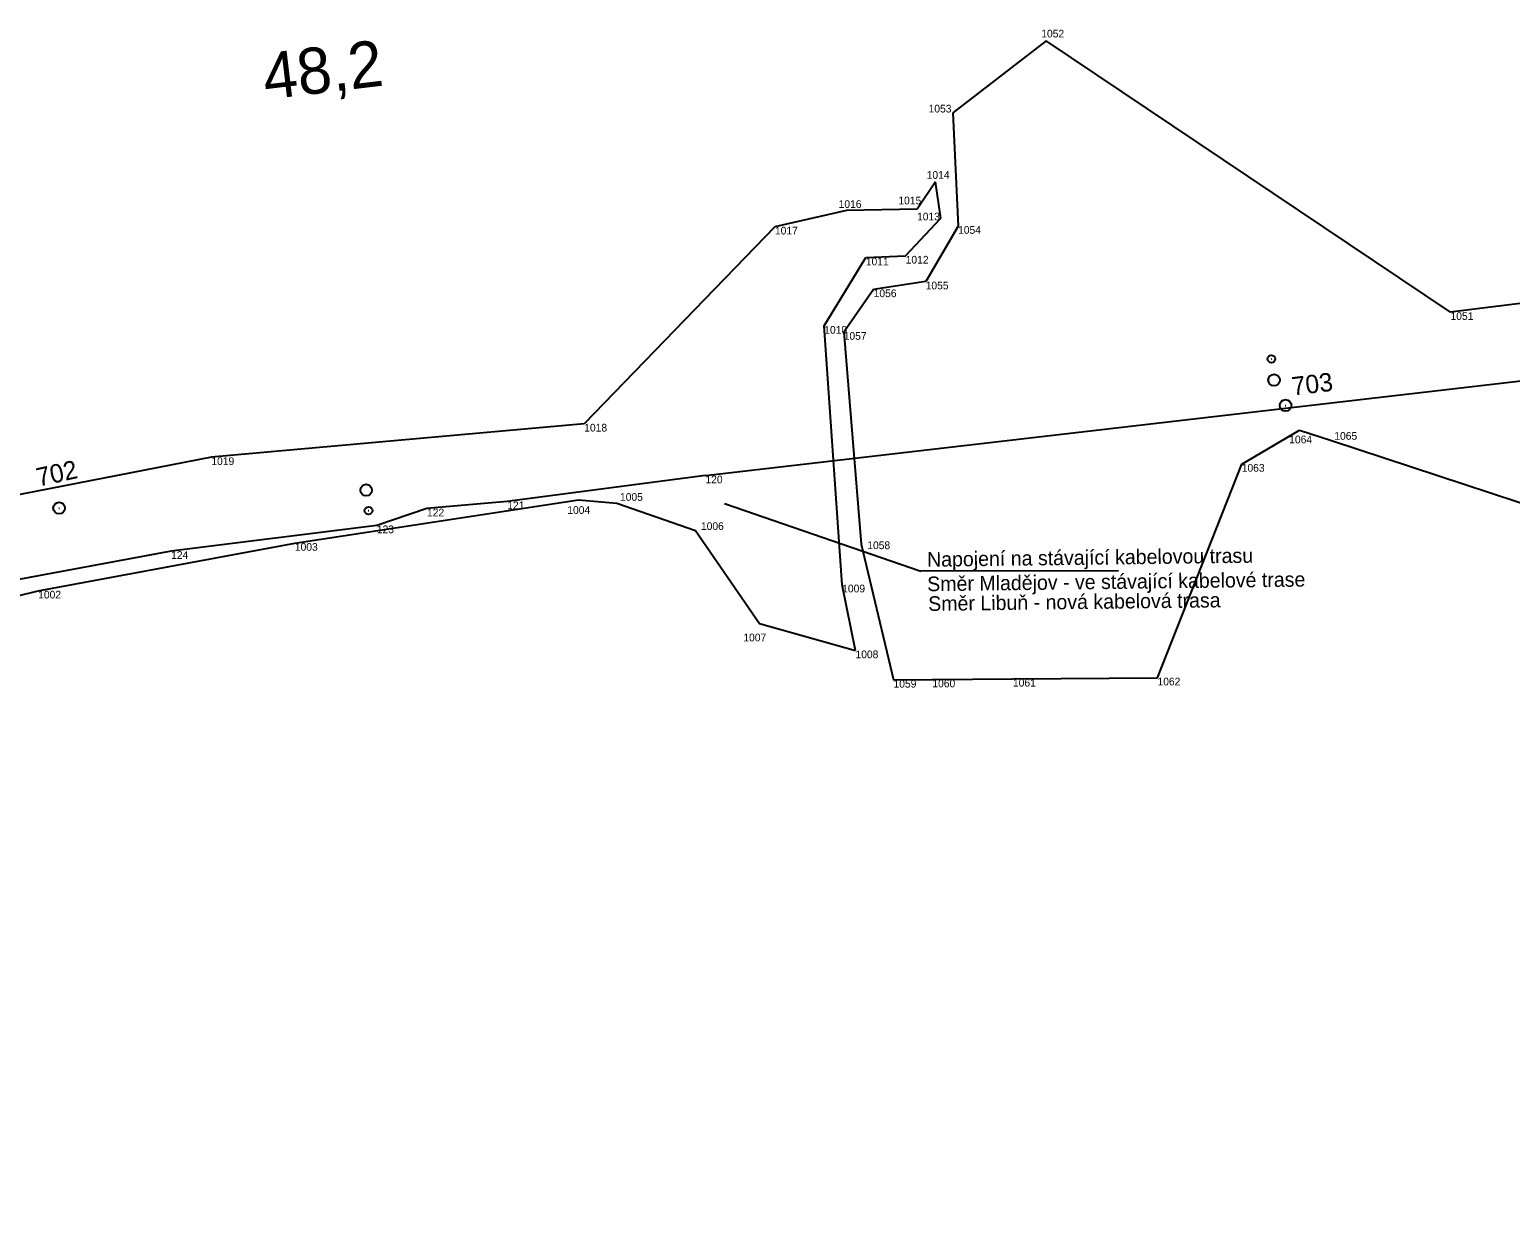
# Model space of a CAD drawing. Extents: x -679938 to -678300, y -1007495 to -1006487.
# Drawn here: x -679308.8 to -679116.3, y -1007081 to -1006925.4 of the extents above; entities that cross this region are included whole.
import ezdxf

# ---------------------------------------------------------------- set-up
doc = ezdxf.new("R2010")
doc.units = 0
for name, color, linetype in [('SSZT nové - lomové body', 7, 'Continuous'), ('SSZT_nové', 7, 'Continuous'), ('Stávající ŽBP', 7, 'Continuous'), ('SŽDC', 7, 'Continuous'), ('SŽDC - body', 7, 'Continuous'), ('Vrstva 7', 7, 'Continuous')]:
    doc.layers.add(name, color=color, linetype=linetype)

msp = doc.modelspace()

# ---------------------------------------------------------------- linework, layer by layer
at = {"layer": 'SSZT nové - lomové body'}
for p, q in [((-679220.94, -1006983.3), (-679220.94, -1006983.3)), ((-679220.94, -1006983.3), (-679220.94, -1006983.3)), ((-679246.69, -1006986.66), (-679246.69, -1006986.66)), ((-679257.12, -1006987.59), (-679257.12, -1006987.59)), ((-679263.64, -1006989.78), (-679263.64, -1006989.78)), ((-679290.37, -1006993.12), (-679290.37, -1006993.12))]:
    msp.add_line(p, q, dxfattribs=at)
at = {"layer": 'SSZT_nové'}
for p in [(-679218.45, -1006986.93), (-679167.27, -1006995.67)]:
    msp.add_line(p, (-679192.94, -1006995.71), dxfattribs=at)
for points in [[(-679220.94, -1006983.3), (-679079.13, -1006966.84), (-679050.01, -1006961.07), (-679026.5, -1006953.22), (-679002.7, -1006941.83), (-678982.82, -1006929.34)], [(-679220.94, -1006983.3), (-679246.69, -1006986.66), (-679257.12, -1006987.59), (-679263.64, -1006989.78), (-679290.37, -1006993.12), (-679314.41, -1006997.58), (-679339.65, -1007005.39), (-679347.7, -1007008.02), (-679359.02, -1007014.04), (-679374.65, -1007024.99), (-679381.38, -1007029.97), (-679393.78, -1007041.11), (-679406.46, -1007055.73), (-679421.12, -1007075.95), (-679445.24, -1007119.78), (-679458.14, -1007141.2), (-679468.52, -1007158.46), (-679472.05, -1007161.83), (-679488.31, -1007180.65), (-679506.94, -1007197.49), (-679535.13, -1007216.77)]]:
    msp.add_lwpolyline(points, dxfattribs=at)
at = {"layer": 'Stávající ŽBP'}
for p, q in [((-679145.61, -1006974.18), (-679145.51, -1006974.17)), ((-679304.97, -1006987.53), (-679304.87, -1006987.51))]:
    msp.add_line(p, q, dxfattribs=at)
for centre in [(-679145.56, -1006974.18), (-679304.92, -1006987.52)]:
    msp.add_circle(centre, 0.756, dxfattribs=at)
at = {"layer": 'SŽDC'}
for p, q in [((-679176.67, -1006926.8), (-679188.77, -1006936.15)), ((-679124.12, -1006962.07), (-679176.67, -1006926.8)), ((-679188.77, -1006936.15), (-679188.11, -1006950.88)), ((-679191.04, -1006945.11), (-679193.44, -1006948.7)), ((-679190.34, -1006949.86), (-679191.04, -1006945.11)), ((-679202.6, -1006948.84), (-679211.91, -1006950.97)), ((-679193.44, -1006948.7), (-679202.6, -1006948.84)), ((-679194.92, -1006954.75), (-679190.34, -1006949.86)), ((-679188.11, -1006950.88), (-679192.32, -1006958.1)), ((-679211.91, -1006950.97), (-679236.69, -1006976.57)), ((-679049.04, -1006952.79), (-679124.12, -1006962.07)), ((-679205.5, -1006963.86), (-679200.1, -1006954.98)), ((-679200.1, -1006954.98), (-679194.92, -1006954.75)), ((-679192.32, -1006958.1), (-679199.08, -1006959.11)), ((-679199.08, -1006959.11), (-679202.97, -1006964.65)), ((-679203.17, -1006997.47), (-679205.5, -1006963.86)), ((-679202.97, -1006964.65), (-679200.7, -1006992.21)), ((-679236.69, -1006976.57), (-679285.14, -1006980.92)), ((-679151.25, -1006981.79), (-679143.73, -1006977.4)), ((-679143.73, -1006977.4), (-679139.6, -1006978.72)), ((-679139.6, -1006978.72), (-679111.47, -1006987.98)), ((-679285.14, -1006980.92), (-679317.07, -1006987.11)), ((-679162.2, -1007009.55), (-679151.25, -1006981.79)), ((-679274.29, -1006992.06), (-679237.43, -1006986.44)), ((-679237.43, -1006986.44), (-679232.46, -1006986.87)), ((-679232.46, -1006986.87), (-679222.24, -1006990.45)), ((-679222.24, -1006990.45), (-679213.91, -1007002.51)), ((-679307.65, -1006998.26), (-679274.29, -1006992.06)), ((-679200.7, -1006992.21), (-679196.5, -1007009.84)), ((-679341.71, -1007006.56), (-679307.65, -1006998.26)), ((-679201.44, -1007006.02), (-679203.17, -1006997.47)), ((-679213.91, -1007002.51), (-679201.44, -1007006.02)), ((-679196.5, -1007009.84), (-679191.45, -1007009.8)), ((-679191.45, -1007009.8), (-679180.98, -1007009.71)), ((-679180.98, -1007009.71), (-679162.2, -1007009.55))]:
    msp.add_line(p, q, dxfattribs=at)
at = {"layer": 'SŽDC - body'}
for p, q in [((-679176.67, -1006926.8), (-679176.67, -1006926.8)), ((-679188.77, -1006936.15), (-679188.77, -1006936.15)), ((-679191.04, -1006945.11), (-679191.04, -1006945.11)), ((-679202.6, -1006948.84), (-679202.6, -1006948.84)), ((-679193.44, -1006948.7), (-679193.44, -1006948.7)), ((-679190.34, -1006949.86), (-679190.34, -1006949.86)), ((-679188.11, -1006950.88), (-679188.11, -1006950.88)), ((-679211.91, -1006950.97), (-679211.91, -1006950.97)), ((-679200.1, -1006954.98), (-679200.1, -1006954.98)), ((-679194.92, -1006954.75), (-679194.92, -1006954.75)), ((-679192.32, -1006958.1), (-679192.32, -1006958.1)), ((-679199.08, -1006959.11), (-679199.08, -1006959.11)), ((-679124.12, -1006962.07), (-679124.12, -1006962.07)), ((-679205.5, -1006963.86), (-679205.5, -1006963.86)), ((-679202.97, -1006964.65), (-679202.97, -1006964.65)), ((-679236.69, -1006976.57), (-679236.69, -1006976.57)), ((-679143.73, -1006977.4), (-679143.73, -1006977.4)), ((-679139.6, -1006978.72), (-679139.6, -1006978.72)), ((-679285.14, -1006980.92), (-679285.14, -1006980.92)), ((-679151.25, -1006981.79), (-679151.25, -1006981.79)), ((-679237.43, -1006986.44), (-679237.43, -1006986.44)), ((-679232.46, -1006986.87), (-679232.46, -1006986.87)), ((-679222.24, -1006990.45), (-679222.24, -1006990.45)), ((-679274.29, -1006992.06), (-679274.29, -1006992.06)), ((-679200.7, -1006992.21), (-679200.7, -1006992.21)), ((-679307.65, -1006998.26), (-679307.65, -1006998.26)), ((-679203.17, -1006997.47), (-679203.17, -1006997.47)), ((-679213.91, -1007002.51), (-679213.91, -1007002.51)), ((-679201.44, -1007006.02), (-679201.44, -1007006.02)), ((-679196.5, -1007009.84), (-679196.5, -1007009.84)), ((-679191.45, -1007009.8), (-679191.45, -1007009.8)), ((-679180.98, -1007009.71), (-679180.98, -1007009.71)), ((-679162.2, -1007009.55), (-679162.2, -1007009.55))]:
    msp.add_line(p, q, dxfattribs=at)
at = {"layer": 'Vrstva 7'}
for p, q in [((-679147.44, -1006968.15), (-679147.34, -1006968.14)), ((-679264.77, -1006987.84), (-679264.67, -1006987.83))]:
    msp.add_line(p, q, dxfattribs=at)
for centre, radius in [((-679147.39, -1006968.14), 0.5), ((-679147.05, -1006970.88), 0.75), ((-679265.03, -1006985.18), 0.75), ((-679264.72, -1006987.84), 0.5)]:
    msp.add_circle(centre, radius, dxfattribs=at)

# ---------------------------------------------------------------- texts
at = {"layer": 'SSZT nové - lomové body'}
for s, p in [('120', (-679220.94, -1006984.3)), ('1', (-679220.94, -1006984.3)), ('121', (-679246.69, -1006987.66)), ('122', (-679257.12, -1006988.59)), ('123', (-679263.64, -1006990.78)), ('124', (-679290.37, -1006994.12))]:
    msp.add_text(s, height=1, dxfattribs=at).set_placement(p)
at = {"layer": 'SSZT_nové'}
for s, p in [('Napojení na stávající kabelovou trasu', (-679192.13, -1006995.14)), ('Směr Mladějov - ve stávající kabelové trase', (-679192.11, -1006998.32)), ('Směr Libuň - nová kabelová trasa', (-679191.98, -1007000.88))]:
    msp.add_text(s, height=1.9, rotation=0.7098, dxfattribs=at).set_placement(p)
at = {"layer": 'Stávající ŽBP'}
for s, rotation, p in [('703', 6.9363, (-679144.6, -1006972.91)), ('702', 12.4287, (-679307.59, -1006984.74))]:
    msp.add_text(s, height=2.4, rotation=rotation, dxfattribs=at).set_placement(p)
at = {"layer": 'SŽDC - body'}
for s, p in [('1052', (-679177.3, -1006926.37)), ('1053', (-679191.94, -1006936.12)), ('1014', (-679192.19, -1006944.74)), ('1016', (-679203.63, -1006948.52)), ('1015', (-679195.87, -1006948.06)), ('1013', (-679193.44, -1006950.14)), ('1054', (-679188.11, -1006951.88)), ('1017', (-679211.91, -1006951.97)), ('1011', (-679200.1, -1006955.98)), ('1012', (-679194.92, -1006955.75)), ('1055', (-679192.32, -1006959.1)), ('1056', (-679199.08, -1006960.11)), ('1051', (-679124.12, -1006963.07)), ('1010', (-679205.5, -1006964.86)), ('1057', (-679202.97, -1006965.65)), ('1018', (-679236.69, -1006977.57)), ('1065', (-679139.22, -1006978.64)), ('1064', (-679145.08, -1006979.1)), ('1019', (-679285.14, -1006981.92)), ('1063', (-679151.25, -1006982.79)), ('1004', (-679238.89, -1006988.27)), ('1005', (-679232.04, -1006986.57)), ('1006', (-679221.52, -1006990.36)), ('1003', (-679274.29, -1006993.06)), ('1058', (-679199.91, -1006992.85)), ('1002', (-679307.65, -1006999.26)), ('1009', (-679203.17, -1006998.47)), ('1007', (-679216.01, -1007004.83)), ('1008', (-679201.44, -1007007.02)), ('1059', (-679196.5, -1007010.84)), ('1060', (-679191.45, -1007010.8)), ('1061', (-679180.98, -1007010.71)), ('1062', (-679162.2, -1007010.55))]:
    msp.add_text(s, height=1, dxfattribs=at).set_placement(p)
at = {"layer": 'Vrstva 7'}
msp.add_text('48,2', height=6, rotation=6.8495, dxfattribs=at).set_placement((-679278.08, -1006934.46))

doc.saveas('drawing.dxf')
